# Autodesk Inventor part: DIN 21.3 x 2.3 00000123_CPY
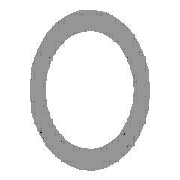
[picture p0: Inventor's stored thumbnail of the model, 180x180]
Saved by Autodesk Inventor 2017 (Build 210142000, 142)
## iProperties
Created: 2017-11
Part Number: DIN 21.3 x 2.3 00000123_CPY
Material: Steel, Mild
Description: Pipe
Document SubType Name: Modeling
Standard: DIN
Designer: iusti
Standard Revision: 2006-07
Standards Organization: DIN
Language: en-US
Size Designation: 21.3 x 2.3
Categories: <MemberInstance><Categories><Category DisplayName="Structural Shapes" InternalName="089c4875-fa83-4c05-b084-43b9cc11f5ed" Mnemonic="GRDR"><CategoryParameter Dis
Stock Number: 21.3 x 2.3
Density: 7.85 g/cm^3
Appearance: Semi-Polished
_CCFamilyMember: 1
_CCFamilyDisplayName: DIN EN 10210-2 - Pipe
_FrameMemberDoc: Frame Member File
_Version: 15.0.0
_GetPNFromCC: 1
IsCustomPart: 1
Author: iusti
G_L: 2570.401 mm
G_W: 21.300 mm
G_H: 21.300 mm
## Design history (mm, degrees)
node "Start plane"
node "End plane"
sketch "Sketch"
  geometry: C1 r 8.35 at (0, 0); C2 r 10.65 at (0, 0); 2 further points
  constraints: 3 coincident, 2 centre point
  dimensions: "d0" = 21.3 diameter of C2 (= G_H); "d1" = 2.3 radial gap between concentric circles of C2 C1 (= G_T)
extrude "Body" new body sketch "Sketch" stored distance "d2" = 2570.40077 (= G_L); taper "d3" = 0 deg
node "Driven Length"
  sketch "Sketch3"
    geometry: L1 (0, 0)-(10, 0) reference
    constraints: 2 end point, 1 horizontal
  workplane "Work Plane3"
  sketch "Sketch4"
    geometry: L1 (-2, 0)-(12, 0) reference; L2 (-2, 2570.401)-(12, 2570.401) reference
    dimensions: "d7" = 2570.40077 distance between parallel lines of L1 L2 (derived)
body "Solid1"
other parameters: "G_H" = 21.3 [user parameter; used in 1 equation term], "G_T" = 2.3 [user parameter; used in 1 equation term], "G_L" = 2570.40077 (= d7) [user parameter; used in 1 equation term], "G_OFFSET_START" = 0 [user parameter; used in 1 equation term], "G_OFFSET_END" = 0 [user parameter; used in 1 equation term], "d4" = 0 (computed from G_OFFSET_START), "d5" = 2570.40077 (= G_OFFSET_END + B_L), "B_L" = 2570.40077 [user parameter; used in 1 equation term], "d6" = 90 deg
